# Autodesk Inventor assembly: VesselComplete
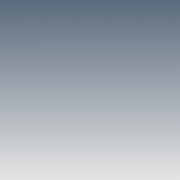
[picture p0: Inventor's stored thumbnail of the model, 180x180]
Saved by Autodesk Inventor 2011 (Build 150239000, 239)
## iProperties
Created: 2010-07
Part Number: VesselComplete
Document SubType Name: Assembly
Designer: mklassen
Author: mklassen
OD: 24.000 in
THK: 0.500 in
LEN: 3.000 ft
SVOFS: 6.000 in
SKLEN: 2.500 ft
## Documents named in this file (1)
- O:\cadd\tutorials\inventor 2011\iLogic\VesselComplete.iam
## Named parameters: SVOFS = 152.4 mm, SKLEN = 762 mm
